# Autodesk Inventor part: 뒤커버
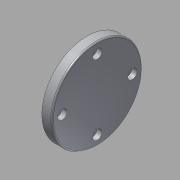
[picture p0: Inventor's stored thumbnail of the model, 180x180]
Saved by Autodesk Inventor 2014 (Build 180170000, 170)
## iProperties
Created: 2015-09
Part Number: 뒤커버
Material: 알루미늄 6061
Document SubType Name: Modeling
Designer: mduedu
Density: 2.71 g/cm^3
Appearance: 알루미늄 - 평지
Mass: 54.0417 g
Surface Area: 84.9688 cm^2
Volume: 19.9416 cm^3
Author: mduedu
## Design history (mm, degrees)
sketch "스케치1"
  geometry: L1 (-15.5, 47)-(-15.5, 78); L2 (-15.5, 78)-(-22.5, 78); L3 (-22.5, 78)-(-22.5, 67); L4 (-25.5, 67)-(-25.5, 47); L5 (-79.5, 39.5)-(-79.5, 54.5) reference; L6 (48.5, 54.5)-(48.5, 39.5) reference; L7 (-79.5, 47)-(48.5, 47); L8 (-22.5, 67)-(-25.5, 67); L9 (-25.5, 47)-(-15.5, 47); 1 further point
  constraints: 14 end point, 4 midpoint, 3 parallel, 1 collinear, 1 point on line, 1 vertical
  dimensions: "d6" = 62 diameter of L2 L7; "d7" = 7 distance of L1.end L2.end; "d8" = 40 diameter of L3.end L7; "d32" = 10 distance between parallel lines of L1 L4
revolve "회전1" sketch "스케치1" stored, may be unused: angle "d4" = 90 deg
sketch "스케치4"
  geometry: C1 r 31 at (0, 0) reference; 2 further points
  constraints: 1 coincident
hole "구멍3" sketch "스케치4" at (0, 0) diameter "d33" = 33; stored, may be unused: countersink angle "d37" = 90 deg, drill point angle "d39" = 0 deg; dims "d34" = 6, "d35" = 4, "d36" = 2, "d38" = 5
fillet "모깎기4" dims "d40" = 1
chamfer "모따기2" distance "d41" = 1; stored, may be unused: second distance "d42" = 2, angle "d43" = 45 deg
sketch "스케치5" dims "d44" = 48
  geometry: C1 r 31 at (0, 0) reference; 6 further points
  constraints: 2 vertical alignment, 1 coincident, 7 other
  dimensions: "d47" = 360 deg dimension on C1.centre point (0, -24) (derived)
sketch "스케치6"
  geometry: 4 further points
hole "구멍4" sketch "스케치6" at (24, 0), (0, 24), (-24, 0), (0, -24) diameter "d49" = 3.4; stored, may be unused: countersink angle "d53" = 90 deg, drill point angle "d55" = 0 deg; dims "d50" = 6, "d51" = 6.5, "d52" = 3.4, "d54" = 8
node "솔리드1"
node "참조1"
node "참조2"
